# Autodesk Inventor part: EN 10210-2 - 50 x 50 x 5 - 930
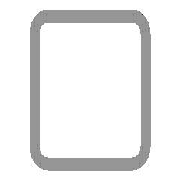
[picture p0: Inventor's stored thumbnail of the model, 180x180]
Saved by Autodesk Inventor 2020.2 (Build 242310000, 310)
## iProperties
Created: 2019-01
Part Number: EN 10210-2 - 50 x 50 x 5 - 930
Material: Stahl, weich
Description: Rohrleitung
Document SubType Name: Modeling
Standard: DIN
Designer: lutzd
Standard Revision: 2006-07
Standards Organization: DIN
Language: de-DE
Size Designation: 50 x 50 x 5
Categories: <MemberInstance><Categories><Category DisplayName="Profile" InternalName="089c4875-fa83-4c05-b084-43b9cc11f5ed" Mnemonic="GRDR"><CategoryParameter DisplayName="
Stock Number: 50 x 50 x 5
Mass: 6371.89 g
Surface Area: 3166.58 cm^2
Volume: 811.706 cm^3
Density: 7.85 g/cm^3
Appearance: Semi-Polished(8)
IsCustomPart: 1
G_L: 930,000 mm
G_W: 50,000 mm
G_H: 50,000 mm
+A57FD075-35F2-4BF9-9B49-C7E21264B223+SCHNITTDETAIL1: Schnittwinkel 90,00 grd
+CA14ADF0-08D3-45AE-8D4E-6F7B36C33411+SCHNITTDETAIL2: Schnittwinkel 90,00 grd
Dimensions: 50x50x930 mm
Mass: 6,372 kg
VLT_Material: Stahl, weich
_CCFamilyMember: 16
_CCFamilyDisplayName: DIN EN 10210-2 (USAS B17.1 quadratisch) - Rohrleitung — In Klammern angegebene Größen wurden aufgehoben
_FrameMemberDoc: Frame Member File
_Version: 15.0.0
_GetPNFromCC: 1
Author: lutzd
Revision Number: -
Title: Rohrleitung
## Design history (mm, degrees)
node "Startebene"
node "Endebene"
sketch "Skizze"
  geometry: L1 (-25, -17.5)-(-25, 17.5); L2 (-17.5, 25)-(17.5, 25); L3 (25, 17.5)-(25, -17.5); L4 (17.5, -25)-(-17.5, -25); L5 (-15, 20)-(15, 20); L6 (20, 15)-(20, -15); L7 (15, -20)-(-15, -20); L8 (-20, -15)-(-20, 15); L9 (0, 37.175)-(0, -37.175) reference; L10 (-37.175, 0)-(37.175, 0) reference; A1 r 7.5 centre (-17.5, -17.5) between (-25, -17.5) and (-17.5, -25); A2 r 7.5 centre (-17.5, 17.5) between (-17.5, 25) and (-25, 17.5); A3 r 7.5 centre (17.5, 17.5) between (25, 17.5) and (17.5, 25); A4 r 7.5 centre (17.5, -17.5) between (17.5, -25) and (25, -17.5); A5 r 5 centre (-15, -15) between (-20, -15) and (-15, -20); A6 r 5 centre (-15, 15) between (-15, 20) and (-20, 15); A7 r 5 centre (15, 15) between (20, 15) and (15, 20); A8 r 5 centre (15, -15) between (15, -20) and (20, -15)
  constraints: 16 end point, 16 point on circle, 16 tangent, 8 centre point, 6 equal radius, 4 parallel, 2 perpendicular, 2 other
  dimensions: "d7" = 7.5 radius of A1 (= G_IR); "d10" = 50 distance between parallel lines of L2 L4 (= G_H); "d11" = 50 distance between parallel lines of L1 L3 (= G_W); "d12" = 5 distance between parallel lines of L3 L6 (= G_T); "d15" = 25 distance between parallel lines of L2 L10 (= 0.5 x d10); "d16" = 25 distance between parallel lines of L9 L3 (= 0.5 x d11); "d19" = 5 radius of A5 (= G_T); "d20" = 5 distance between parallel lines of L4 L7 (= G_T)
extrude "Körper" new body sketch "Skizze" stored distance "d3" = 930 (= G_L); taper "d4" = 0 deg
node "Driven Length"
  sketch "Sketch3"
    geometry: L1 (0, 0)-(10, 0) reference
    constraints: 2 end point, 1 horizontal
  workplane "Work Plane3"
  sketch "Sketch4"
    geometry: L1 (-2, 50)-(12, 50) reference; L2 (-2, 980)-(12, 980) reference
    dimensions: "d18" = 930 distance between parallel lines of L1 L2 (derived)
workplane "Arbeitsebene4"
feature "Trennen1"
workplane "Arbeitsebene5"
feature "Trennen2"
sketch "Skizze5"
  geometry: L1 (35, 930)-(0, 930) reference; L2 (17.5, 930)-(17.5, 621.475); 3 further points
  constraints: 2 end point, 1 coincident, 1 midpoint, 1 point on line, 1 vertical
  dimensions: "d21" = 203 distance of point (17.5, 621.475) point (17.5, 824.475); "d22" = 105.525 distance from line of point (17.5, 824.475) L1
hole "Bohrung1" sketch "Skizze5" at (17.5, 621.475), (17.5, 824.475) diameter "d23" = 6.647; stored, may be unused: countersink angle "d27" = 90 deg, drill point angle "d29" = 118 deg; dims "d24" = 16, "d25" = 17.3, "d26" = 2, "d28" = 22.2
body "Solid1"
other parameters: "G_W" = 50 [user parameter; used in 1 equation term], "G_H" = 50 [user parameter; used in 1 equation term], "G_T" = 5 [user parameter; used in 3 equation terms], "G_IR" = 7.5 [user parameter; used in 1 equation term], "G_L" = 930 (= d18) [user parameter; used in 1 equation term], "d17" = 90 deg
